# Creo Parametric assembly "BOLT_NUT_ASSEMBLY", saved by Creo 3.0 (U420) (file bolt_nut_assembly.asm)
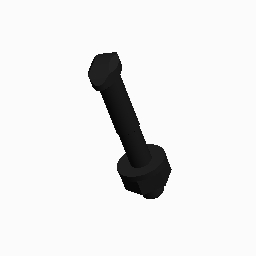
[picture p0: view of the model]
Units: millimeter Kilogram Sec (mmKs); MM, KILOGRAM, SECS

Created from: INLBS_ASM_DESIGN.ASM

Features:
  1. datum plane "ASM_RIGHT"
  2. datum plane "ASM_TOP"
  3. datum plane "ASM_FRONT"
  4. coordinate system
  5. component "ROD_BOLT"
  6. component "ROD_NUT"

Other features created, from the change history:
  component interface "INTFC001"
